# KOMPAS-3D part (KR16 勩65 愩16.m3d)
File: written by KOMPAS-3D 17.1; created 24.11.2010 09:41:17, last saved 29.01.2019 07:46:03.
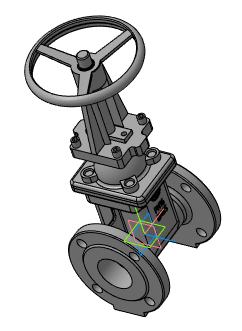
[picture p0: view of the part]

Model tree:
1. Плоскость XY
2. Плоскость ZX
3. Плоскость ZY
4. Ось X
5. Ось Y
6. Ось Z
7. Начало координат
8. Операция без истории:2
